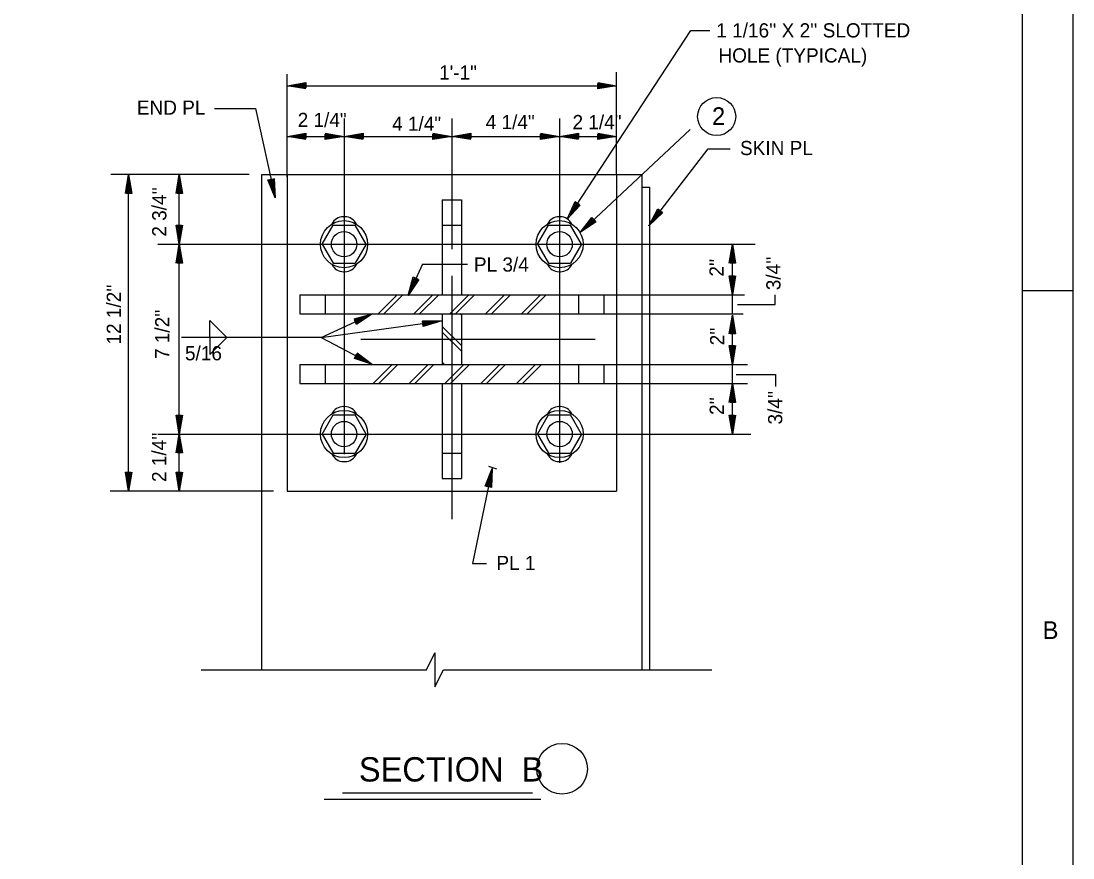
# Model space of a CAD drawing. Extents: x 0.1 to 13.5, y 0.1 to 9.5.
# Drawn here: x 10 to 13.457, y 2.925 to 5.677 of the extents above; entities that cross this region are included whole.
import ezdxf

# ---------------------------------------------------------------- set-up
doc = ezdxf.new("R2010")
doc.units = 0
for name, color, linetype in [('Level 1', 7, 'Continuous'), ('Level 2', 7, 'Continuous'), ('Level 25', 7, 'Continuous'), ('Level 3', 7, 'Continuous'), ('Level 4', 7, 'Continuous'), ('Level 44', 7, 'Continuous'), ('Level 50', 7, 'Continuous')]:
    doc.layers.add(name, color=color, linetype=linetype)

msp = doc.modelspace()

# ---------------------------------------------------------------- linework, layer by layer
at = {"layer": 'Level 1'}
msp.add_line((13.2904, 4.7903), (13.4571, 4.7903), dxfattribs=at)
for points in [[(0.1238, 9.4569), (13.4571, 9.4569), (13.4571, 0.1236), (0.1238, 0.1236)], [(0.6238, 9.2903), (13.2904, 9.2903), (13.2904, 0.2903), (0.6238, 0.2903)]]:
    msp.add_lwpolyline(points, close=True, dxfattribs=at)
msp.add_lwpolyline([(11.3324, 3.5433), (11.3604, 3.5995), (11.3604, 3.4872), (11.3885, 3.5433)], dxfattribs=at)
at = {"layer": 'Level 2'}
for p, q in [((10.8741, 5.4643), (11.9574, 5.4643)), ((11.0616, 5.3566), (11.0616, 4.2531)), ((11.4158, 5.3566), (11.4158, 4.9263)), ((11.7699, 5.3566), (11.7699, 4.2246)), ((10.8741, 5.2976), (11.0616, 5.2976)), ((11.0616, 5.2976), (11.4158, 5.2976)), ((11.4158, 5.2976), (11.7699, 5.2976)), ((11.7699, 5.2976), (11.9574, 5.2976)), ((10.3533, 4.1309), (10.3533, 5.1726)), ((10.5199, 4.943), (10.5199, 5.1726)), ((10.7908, 3.5433), (10.7908, 5.1726)), ((10.7908, 5.1726), (12.0408, 5.1726)), ((10.8741, 5.1726), (10.8741, 4.1309)), ((11.9574, 5.1726), (11.9574, 4.1309)), ((12.0408, 3.5433), (12.0408, 5.1726)), ((12.0408, 5.1309), (12.0668, 5.1309)), ((12.0668, 3.5433), (12.0668, 5.1309)), ((11.3845, 5.0893), (11.447, 5.0893)), ((11.3845, 5.0893), (11.3845, 4.7768)), ((11.447, 5.0893), (11.447, 4.7768)), ((11.0594, 5.0332), (11.0642, 5.0332)), ((11.7678, 5.0332), (11.7725, 5.0332)), ((10.9893, 4.943), (11.0256, 5.0058)), ((11.0256, 5.0058), (11.0977, 5.0058)), ((11.1339, 4.943), (11.0977, 5.0058)), ((11.3845, 5.0059), (11.447, 5.0059)), ((11.6977, 4.943), (11.7339, 5.0058)), ((11.7339, 5.0058), (11.806, 5.0058)), ((11.8422, 4.943), (11.806, 5.0058)), ((10.4497, 4.943), (12.4128, 4.943)), ((10.5199, 4.3188), (10.5199, 4.943)), ((10.9893, 4.943), (11.0256, 4.8803)), ((11.0616, 4.943), (11.0616, 4.943)), ((11.0616, 4.943), (11.0616, 4.943)), ((11.0616, 4.943), (11.0616, 4.943)), ((11.1339, 4.943), (11.0977, 4.8803)), ((11.6977, 4.943), (11.7339, 4.8803)), ((11.7699, 4.943), (11.7699, 4.943)), ((11.7699, 4.943), (11.7699, 4.943)), ((11.7699, 4.943), (11.7699, 4.943)), ((11.7699, 4.943), (11.7699, 4.943)), ((11.8422, 4.943), (11.806, 4.8803)), ((12.3377, 4.7768), (12.3377, 4.943)), ((11.0256, 4.8803), (11.0977, 4.8803)), ((11.7339, 4.8803), (11.806, 4.8803)), ((11.0597, 4.8526), (11.0642, 4.8525)), ((11.7681, 4.8526), (11.7725, 4.8525)), ((11.4158, 4.8387), (11.4158, 4.0391)), ((10.9158, 4.7768), (11.9158, 4.7768)), ((10.9158, 4.7768), (10.9158, 4.7143)), ((10.9991, 4.7768), (10.9991, 4.7143)), ((11.8324, 4.7768), (11.8324, 4.7143)), ((11.9158, 4.7768), (11.9158, 4.7143)), ((12.3377, 4.7143), (12.3377, 4.7768)), ((10.9158, 4.7143), (11.9158, 4.7143)), ((11.3845, 4.7143), (11.3845, 4.5476)), ((11.447, 4.7143), (11.447, 4.5476)), ((12.3377, 4.5476), (12.3377, 4.7102)), ((10.9158, 4.5476), (11.9158, 4.5476)), ((10.9158, 4.5476), (10.9158, 4.4851)), ((10.9991, 4.5476), (10.9991, 4.4851)), ((11.8324, 4.5476), (11.8324, 4.4851)), ((11.9158, 4.5476), (11.9158, 4.4851)), ((12.3377, 4.4851), (12.3377, 4.5476)), ((10.9158, 4.4851), (11.9158, 4.4851)), ((11.3845, 4.4851), (11.3845, 4.1726)), ((11.447, 4.4851), (11.447, 4.1726)), ((12.3377, 4.3188), (12.3377, 4.4851)), ((11.0594, 4.4089), (11.0642, 4.4089)), ((11.7678, 4.4089), (11.7725, 4.4089)), ((10.9893, 4.3188), (11.0256, 4.3816)), ((11.0256, 4.3816), (11.0977, 4.3816)), ((11.1339, 4.3188), (11.0977, 4.3816)), ((11.6977, 4.3188), (11.7339, 4.3816)), ((11.7339, 4.3816), (11.806, 4.3816)), ((11.8422, 4.3188), (11.806, 4.3816)), ((10.4497, 4.3188), (12.3985, 4.3188)), ((10.5199, 4.1309), (10.5199, 4.3188)), ((10.9893, 4.3188), (11.0256, 4.2561)), ((11.0616, 4.3188), (11.0616, 4.3188)), ((11.0616, 4.3188), (11.0616, 4.3188)), ((11.0616, 4.3188), (11.0616, 4.3188)), ((11.0616, 4.3188), (11.0616, 4.3188)), ((11.0616, 4.3188), (11.0616, 4.3188)), ((11.1339, 4.3188), (11.0977, 4.2561)), ((11.6977, 4.3188), (11.7339, 4.2561)), ((11.7699, 4.3188), (11.7699, 4.3188)), ((11.7699, 4.3188), (11.7699, 4.3188)), ((11.7699, 4.3188), (11.7699, 4.3188)), ((11.7699, 4.3188), (11.7699, 4.3188)), ((11.7699, 4.3188), (11.7699, 4.3188)), ((11.7699, 4.3188), (11.7699, 4.3188)), ((11.8422, 4.3188), (11.806, 4.2561)), ((11.0256, 4.2561), (11.0977, 4.2561)), ((11.3845, 4.2559), (11.447, 4.2559)), ((11.7339, 4.2561), (11.806, 4.2561)), ((11.0597, 4.2284), (11.0642, 4.2283)), ((11.7681, 4.2284), (11.7725, 4.2283)), ((11.3845, 4.1726), (11.447, 4.1726)), ((10.8741, 4.1309), (11.9574, 4.1309)), ((10.592, 3.5433), (11.3324, 3.5433)), ((11.3885, 3.5433), (12.2705, 3.5433))]:
    msp.add_line(p, q, dxfattribs=at)
for points in [[(11.1733, 4.7143), (11.2359, 4.7768)], [(11.1922, 4.7143), (11.2547, 4.7768)], [(11.2912, 4.7143), (11.3537, 4.7768)], [(11.31, 4.7143), (11.3726, 4.7768)], [(11.4091, 4.7143), (11.4716, 4.7768)], [(11.4279, 4.7143), (11.4904, 4.7768)], [(11.5269, 4.7143), (11.5894, 4.7768)], [(11.5458, 4.7143), (11.6083, 4.7768)], [(11.6447, 4.7143), (11.7073, 4.7768)], [(11.6636, 4.7143), (11.7261, 4.7768)], [(11.447, 4.7093), (11.442, 4.7143)], [(11.447, 4.6103), (11.3845, 4.6728)], [(11.447, 4.5914), (11.3845, 4.6539)], [(11.1572, 4.4851), (11.2197, 4.5476)], [(11.1761, 4.4851), (11.2386, 4.5476)], [(11.2751, 4.4851), (11.3376, 4.5476)], [(11.2939, 4.4851), (11.3564, 4.5476)], [(11.3918, 4.5476), (11.3845, 4.5549)], [(11.3929, 4.4851), (11.4554, 4.5476)], [(11.4118, 4.4851), (11.4743, 4.5476)], [(11.5108, 4.4851), (11.5733, 4.5476)], [(11.5296, 4.4851), (11.5921, 4.5476)], [(11.6286, 4.4851), (11.6911, 4.5476)], [(11.6475, 4.4851), (11.71, 4.5476)]]:
    msp.add_lwpolyline(points, dxfattribs=at)
for centre, radius in [((11.0616, 4.943), 0.0775), ((11.7699, 4.943), 0.0775), ((11.0616, 4.943), 0.0417), ((11.7699, 4.943), 0.0417), ((11.0616, 4.3188), 0.0775), ((11.7699, 4.3188), 0.0775), ((11.0616, 4.3188), 0.0417), ((11.7699, 4.3188), 0.0417)]:
    msp.add_circle(centre, radius, dxfattribs=at)
for centre, start, end in [((11.0594, 4.9915), 90, 154.2596), ((11.0642, 4.9915), 25.204, 90), ((11.7678, 4.9915), 90, 154.2596), ((11.7725, 4.9915), 25.204, 90), ((11.0597, 4.8943), 205.7404, 270), ((11.0642, 4.8942), 270, 334.796), ((11.7681, 4.8943), 205.7404, 270), ((11.7725, 4.8942), 270, 334.796), ((11.0594, 4.3673), 90, 154.2596), ((11.0642, 4.3673), 25.204, 90), ((11.7678, 4.3673), 90, 154.2596), ((11.7725, 4.3673), 25.204, 90), ((11.0597, 4.2701), 205.7404, 270), ((11.0642, 4.27), 270, 334.796), ((11.7681, 4.2701), 205.7404, 270), ((11.7725, 4.27), 270, 334.796)]:
    msp.add_arc(centre, 0.0417, start, end, dxfattribs=at)
at = {"layer": 'Level 25'}
msp.add_line((11.117, 4.6309), (11.8864, 4.6309), dxfattribs=at)
at = {"layer": 'Level 3'}
for p, q in [((11.8047, 5.0399), (12.2017, 5.646)), ((12.2017, 5.646), (12.2637, 5.646)), ((10.8741, 5.1647), (10.8741, 5.5018)), ((11.9574, 5.1725), (11.9574, 5.5087)), ((11.3984, 5.2976), (11.3984, 5.2976)), ((11.4158, 5.2976), (11.4158, 5.2976)), ((11.4158, 5.2976), (11.4158, 5.2976)), ((11.4331, 5.2976), (11.4331, 5.2976)), ((12.1989, 5.3201), (11.8378, 4.9811)), ((12.0632, 5.0038), (12.2578, 5.2565)), ((12.2578, 5.2565), (12.3305, 5.2565)), ((10.8312, 5.1127), (10.8312, 5.1127)), ((10.8349, 5.0958), (10.8349, 5.0958)), ((11.7952, 5.0254), (11.7952, 5.0254)), ((11.8047, 5.0399), (11.8047, 5.0399)), ((12.0738, 5.0175), (12.0738, 5.0175)), ((11.8378, 4.9811), (11.8378, 4.9811)), ((11.8504, 4.993), (11.8504, 4.993)), ((12.0632, 5.0038), (12.0632, 5.0038)), ((10.5199, 4.9604), (10.5199, 4.9604)), ((10.5199, 4.943), (10.5199, 4.943)), ((10.5199, 4.943), (10.5199, 4.943)), ((10.5199, 4.9257), (10.5199, 4.9257)), ((12.3377, 4.943), (12.3377, 4.943)), ((12.3377, 4.9257), (12.3377, 4.9257)), ((11.3193, 4.8775), (11.2721, 4.7746)), ((11.3193, 4.8775), (11.4672, 4.8775)), ((11.2721, 4.7746), (11.2721, 4.7746)), ((11.2793, 4.7904), (11.2793, 4.7904)), ((11.7119, 4.7768), (12.3772, 4.7768)), ((12.3377, 4.7941), (12.3377, 4.7941)), ((12.3377, 4.7768), (12.3377, 4.7768)), ((12.478, 4.7446), (12.478, 4.7762)), ((12.3541, 4.7446), (12.478, 4.7446)), ((10.9863, 4.6366), (11.1554, 4.7143)), ((11.1396, 4.707), (11.1396, 4.707)), ((11.1554, 4.7143), (11.1554, 4.7143)), ((11.7159, 4.7143), (12.3736, 4.7143)), ((12.3377, 4.7102), (12.3377, 4.7102)), ((10.9863, 4.6366), (11.3825, 4.6906)), ((11.3653, 4.6883), (11.3653, 4.6883)), ((11.3825, 4.6906), (11.3825, 4.6906)), ((12.3377, 4.6928), (12.3377, 4.6928)), ((10.9863, 4.6366), (11.1554, 4.5476)), ((12.3377, 4.5649), (12.3377, 4.5649)), ((11.14, 4.5557), (11.14, 4.5557)), ((11.1554, 4.5476), (11.1554, 4.5476)), ((11.7198, 4.5476), (12.3879, 4.5476)), ((12.3377, 4.5476), (12.3377, 4.5476)), ((12.3506, 4.5151), (12.4792, 4.5151)), ((12.4792, 4.5151), (12.4792, 4.4749)), ((11.7198, 4.4851), (12.3879, 4.4851)), ((12.3377, 4.4851), (12.3377, 4.4851)), ((12.3377, 4.4678), (12.3377, 4.4678)), ((10.5199, 4.3362), (10.5199, 4.3362)), ((12.3377, 4.3362), (12.3377, 4.3362)), ((10.5199, 4.3188), (10.5199, 4.3188)), ((10.5199, 4.3188), (10.5199, 4.3188)), ((10.5199, 4.3015), (10.5199, 4.3015)), ((12.3377, 4.3188), (12.3377, 4.3188)), ((11.5485, 4.2059), (11.4835, 3.8932)), ((11.5362, 4.2129), (11.5626, 4.2041)), ((11.545, 4.1889), (11.545, 4.1889)), ((11.5485, 4.2059), (11.5485, 4.2059)), ((10.8295, 4.1309), (10.2927, 4.1309)), ((10.3533, 4.1483), (10.3533, 4.1483)), ((10.3533, 4.1309), (10.3533, 4.1309)), ((10.5199, 4.1483), (10.5199, 4.1483)), ((10.5199, 4.1309), (10.5199, 4.1309)), ((11.4835, 3.8932), (11.5296, 3.8932)), ((10.9963, 3.1181), (11.7082, 3.1181)), ((11.0568, 3.139), (11.6814, 3.139))]:
    msp.add_line(p, q, dxfattribs=at)
for points in [[(10.6356, 5.389), (10.7704, 5.389), (10.8349, 5.0958)], [(11.3534, 5.3079), (11.4158, 5.2976), (11.3534, 5.2873), (11.3534, 5.3049), (11.3984, 5.2976), (11.3561, 5.2906), (11.3561, 5.3019), (11.3818, 5.2976), (11.3588, 5.2939), (11.3588, 5.2986), (11.3644, 5.2976)], [(11.4781, 5.2873), (11.4158, 5.2976), (11.4781, 5.3079), (11.4781, 5.2903), (11.4331, 5.2976), (11.4754, 5.3046), (11.4754, 5.2933), (11.4498, 5.2976), (11.4728, 5.3013), (11.4728, 5.2966), (11.4671, 5.2976)], [(10.8316, 5.1589), (10.8349, 5.0958), (10.8114, 5.1544), (10.8287, 5.1582), (10.8312, 5.1127), (10.8153, 5.1525), (10.8263, 5.155), (10.8276, 5.129), (10.8191, 5.1506), (10.8237, 5.1516), (10.8239, 5.1459)], [(11.838, 5.0719), (11.7952, 5.0254), (11.8208, 5.0832), (11.8355, 5.0736), (11.8047, 5.0399), (11.8221, 5.0792), (11.8316, 5.073), (11.8139, 5.0539), (11.8234, 5.0751), (11.8273, 5.0726), (11.8234, 5.0684)], [(12.1094, 5.0469), (12.0632, 5.0038), (12.093, 5.0595), (12.107, 5.0487), (12.0738, 5.0175), (12.094, 5.0554), (12.103, 5.0484), (12.0839, 5.0308), (12.0951, 5.0512), (12.0988, 5.0484), (12.0945, 5.0445)], [(11.8903, 5.0163), (11.8378, 4.9811), (11.8761, 5.0313), (11.8882, 5.0184), (11.8504, 4.993), (11.8765, 5.0271), (11.8842, 5.0188), (11.8626, 5.0044), (11.8768, 5.0228), (11.88, 5.0194), (11.8752, 5.0163)], [(10.5303, 5.0054), (10.5199, 4.943), (10.5096, 5.0054), (10.5273, 5.0054), (10.5199, 4.9604), (10.5129, 5.0027), (10.5243, 5.0027), (10.5199, 4.977), (10.5163, 5), (10.5209, 5), (10.5199, 4.9944)], [(10.5096, 4.8807), (10.5199, 4.943), (10.5303, 4.8807), (10.5126, 4.8807), (10.5199, 4.9257), (10.5269, 4.8834), (10.5156, 4.8834), (10.5199, 4.909), (10.5236, 4.886), (10.5189, 4.886), (10.5199, 4.8917)], [(12.3273, 4.8807), (12.3377, 4.943), (12.348, 4.8807), (12.3303, 4.8807), (12.3377, 4.9257), (12.3447, 4.8834), (12.3333, 4.8834), (12.3377, 4.909), (12.3413, 4.886), (12.3367, 4.886), (12.3377, 4.8917)], [(11.3074, 4.827), (11.2721, 4.7746), (11.2887, 4.8356), (11.3047, 4.8282), (11.2793, 4.7904), (11.2906, 4.8318), (11.3009, 4.827), (11.2862, 4.8055), (11.2925, 4.828), (11.2967, 4.826), (11.2935, 4.8213)], [(12.348, 4.8391), (12.3377, 4.7768), (12.3273, 4.8391), (12.345, 4.8391), (12.3377, 4.7941), (12.3307, 4.8364), (12.342, 4.8364), (12.3377, 4.8108), (12.334, 4.8338), (12.3387, 4.8338), (12.3377, 4.8281)], [(11.0944, 4.6976), (11.1554, 4.7143), (11.103, 4.6789), (11.0957, 4.6949), (11.1396, 4.707), (11.1041, 4.683), (11.0993, 4.6933), (11.1245, 4.7001), (11.1051, 4.6871), (11.1032, 4.6914), (11.1087, 4.6928)], [(12.3273, 4.6478), (12.3377, 4.7102), (12.348, 4.6478), (12.3303, 4.6478), (12.3377, 4.6928), (12.3447, 4.6505), (12.3333, 4.6505), (12.3377, 4.6762), (12.3413, 4.6532), (12.3367, 4.6532), (12.3377, 4.6588)], [(11.3193, 4.6924), (11.3825, 4.6906), (11.3221, 4.672), (11.3197, 4.6895), (11.3653, 4.6883), (11.3243, 4.6756), (11.3228, 4.6869), (11.3488, 4.686), (11.3265, 4.6793), (11.3259, 4.6839), (11.3316, 4.6837)], [(12.348, 4.6099), (12.3377, 4.5476), (12.3273, 4.6099), (12.345, 4.6099), (12.3377, 4.5649), (12.3307, 4.6073), (12.342, 4.6073), (12.3377, 4.5816), (12.334, 4.6046), (12.3387, 4.6046), (12.3377, 4.5989)], [(11.105, 4.5858), (11.1554, 4.5476), (11.0954, 4.5675), (11.1036, 4.5831), (11.14, 4.5557), (11.0993, 4.5692), (11.1046, 4.5792), (11.1253, 4.5634), (11.1032, 4.5709), (11.1054, 4.575), (11.1099, 4.5715)], [(12.3273, 4.4228), (12.3377, 4.4851), (12.348, 4.4228), (12.3303, 4.4228), (12.3377, 4.4678), (12.3447, 4.4254), (12.3333, 4.4254), (12.3377, 4.4511), (12.3413, 4.4281), (12.3367, 4.4281), (12.3377, 4.4338)], [(10.5303, 4.3812), (10.5199, 4.3188), (10.5096, 4.3812), (10.5273, 4.3812), (10.5199, 4.3362), (10.5129, 4.3785), (10.5243, 4.3785), (10.5199, 4.3528), (10.5163, 4.3758), (10.5209, 4.3758), (10.5199, 4.3702)], [(12.348, 4.3812), (12.3377, 4.3188), (12.3273, 4.3812), (12.345, 4.3812), (12.3377, 4.3362), (12.3307, 4.3785), (12.342, 4.3785), (12.3377, 4.3528), (12.334, 4.3758), (12.3387, 4.3758), (12.3377, 4.3702)], [(10.5096, 4.2565), (10.5199, 4.3188), (10.5303, 4.2565), (10.5126, 4.2565), (10.5199, 4.3015), (10.5269, 4.2592), (10.5156, 4.2592), (10.5199, 4.2848), (10.5236, 4.2618), (10.5189, 4.2618), (10.5199, 4.2675)], [(10.3636, 4.1933), (10.3533, 4.1309), (10.3429, 4.1933), (10.3606, 4.1933), (10.3533, 4.1483), (10.3463, 4.1906), (10.3576, 4.1906), (10.3533, 4.1649), (10.3496, 4.1879), (10.3543, 4.1879), (10.3533, 4.1823)], [(10.5303, 4.1933), (10.5199, 4.1309), (10.5096, 4.1933), (10.5273, 4.1933), (10.5199, 4.1483), (10.5129, 4.1906), (10.5243, 4.1906), (10.5199, 4.1649), (10.5163, 4.1879), (10.5209, 4.1879), (10.5199, 4.1823)], [(11.5257, 4.1469), (11.5485, 4.2059), (11.5459, 4.1427), (11.5287, 4.1463), (11.545, 4.1889), (11.5432, 4.146), (11.5321, 4.1483), (11.5416, 4.1726), (11.5405, 4.1493), (11.5359, 4.1503), (11.5381, 4.1556)]]:
    msp.add_lwpolyline(points, dxfattribs=at)
for centre, radius in [((12.2861, 5.3629), 0.0625), ((11.7781, 3.2179), 0.0833)]:
    msp.add_circle(centre, radius, dxfattribs=at)
at = {"layer": 'Level 4'}
for p, q in [((10.6208, 4.6923), (10.6767, 4.6364)), ((10.6208, 4.636), (10.6208, 4.6923)), ((10.9863, 4.6366), (10.527, 4.6366)), ((10.6208, 4.6372), (10.6208, 4.5809)), ((10.6208, 4.5809), (10.6767, 4.6368))]:
    msp.add_line(p, q, dxfattribs=at)
at = {"layer": 'Level 44'}
msp.add_line((10.7499, 5.1726), (10.2947, 5.1726), dxfattribs=at)
at = {"layer": 'Level 50'}
for p, q in [((10.8741, 5.4643), (10.8741, 5.4643)), ((10.8914, 5.4643), (10.8914, 5.4643)), ((11.9401, 5.4643), (11.9401, 5.4643)), ((11.9574, 5.4643), (11.9574, 5.4643)), ((10.8741, 5.2976), (10.8741, 5.2976)), ((10.8914, 5.2976), (10.8914, 5.2976)), ((11.0443, 5.2976), (11.0443, 5.2976)), ((11.0616, 5.2976), (11.0616, 5.2976)), ((11.0616, 5.2976), (11.0616, 5.2976)), ((11.0616, 5.2976), (11.0616, 5.2976)), ((11.0789, 5.2976), (11.0789, 5.2976)), ((11.0789, 5.2976), (11.0789, 5.2976)), ((11.7526, 5.2976), (11.7526, 5.2976)), ((11.7699, 5.2976), (11.7699, 5.2976)), ((11.7699, 5.2976), (11.7699, 5.2976)), ((11.7873, 5.2976), (11.7873, 5.2976)), ((11.9401, 5.2976), (11.9401, 5.2976)), ((11.9574, 5.2976), (11.9574, 5.2976)), ((10.3533, 5.1726), (10.3533, 5.1726)), ((10.3533, 5.1726), (10.3533, 5.1726)), ((10.3533, 5.1553), (10.3533, 5.1553)), ((10.3533, 5.1553), (10.3533, 5.1553)), ((10.5199, 5.1726), (10.5199, 5.1726)), ((10.5199, 5.1726), (10.5199, 5.1726)), ((10.5199, 5.1553), (10.5199, 5.1553)), ((10.5199, 5.1553), (10.5199, 5.1553))]:
    msp.add_line(p, q, dxfattribs=at)
for points in [[(10.9364, 5.4539), (10.8741, 5.4643), (10.9364, 5.4746), (10.9364, 5.4569), (10.8914, 5.4643), (10.9338, 5.4713), (10.9338, 5.4599), (10.9081, 5.4643), (10.9311, 5.4679), (10.9311, 5.4633), (10.9254, 5.4643)], [(11.8951, 5.4746), (11.9574, 5.4643), (11.8951, 5.4539), (11.8951, 5.4716), (11.9401, 5.4643), (11.8978, 5.4573), (11.8978, 5.4686), (11.9234, 5.4643), (11.9004, 5.4606), (11.9004, 5.4653), (11.9061, 5.4643)], [(10.9364, 5.2873), (10.8741, 5.2976), (10.9364, 5.3079), (10.9364, 5.2903), (10.8914, 5.2976), (10.9338, 5.3046), (10.9338, 5.2933), (10.9081, 5.2976), (10.9311, 5.3013), (10.9311, 5.2966), (10.9254, 5.2976)], [(10.9993, 5.3079), (11.0616, 5.2976), (10.9993, 5.2873), (10.9993, 5.3049), (11.0443, 5.2976), (11.0019, 5.2906), (11.0019, 5.3019), (11.0276, 5.2976), (11.0046, 5.2939), (11.0046, 5.2986), (11.0103, 5.2976)], [(11.1239, 5.2873), (11.0616, 5.2976), (11.1239, 5.3079), (11.1239, 5.2903), (11.0789, 5.2976), (11.1213, 5.3046), (11.1213, 5.2933), (11.0956, 5.2976), (11.1186, 5.3013), (11.1186, 5.2966), (11.1129, 5.2976)], [(11.1239, 5.2873), (11.0616, 5.2976), (11.1239, 5.3079), (11.1239, 5.2903), (11.0789, 5.2976), (11.1213, 5.3046), (11.1213, 5.2933), (11.0956, 5.2976), (11.1186, 5.3013), (11.1186, 5.2966), (11.1129, 5.2976)], [(11.7076, 5.3079), (11.7699, 5.2976), (11.7076, 5.2873), (11.7076, 5.3049), (11.7526, 5.2976), (11.7103, 5.2906), (11.7103, 5.3019), (11.7359, 5.2976), (11.7129, 5.2939), (11.7129, 5.2986), (11.7186, 5.2976)], [(11.8323, 5.2873), (11.7699, 5.2976), (11.8323, 5.3079), (11.8323, 5.2903), (11.7873, 5.2976), (11.8296, 5.3046), (11.8296, 5.2933), (11.8039, 5.2976), (11.8269, 5.3013), (11.8269, 5.2966), (11.8213, 5.2976)], [(11.8951, 5.3079), (11.9574, 5.2976), (11.8951, 5.2873), (11.8951, 5.3049), (11.9401, 5.2976), (11.8978, 5.2906), (11.8978, 5.3019), (11.9234, 5.2976), (11.9004, 5.2939), (11.9004, 5.2986), (11.9061, 5.2976)], [(10.3429, 5.1103), (10.3533, 5.1726), (10.3636, 5.1103), (10.3459, 5.1103), (10.3533, 5.1553), (10.3603, 5.1129), (10.3489, 5.1129), (10.3533, 5.1386), (10.3569, 5.1156), (10.3523, 5.1156), (10.3533, 5.1213)], [(10.3429, 5.1103), (10.3533, 5.1726), (10.3636, 5.1103), (10.3459, 5.1103), (10.3533, 5.1553), (10.3603, 5.1129), (10.3489, 5.1129), (10.3533, 5.1386), (10.3569, 5.1156), (10.3523, 5.1156), (10.3533, 5.1213)], [(10.5096, 5.1103), (10.5199, 5.1726), (10.5303, 5.1103), (10.5126, 5.1103), (10.5199, 5.1553), (10.5269, 5.1129), (10.5156, 5.1129), (10.5199, 5.1386), (10.5236, 5.1156), (10.5189, 5.1156), (10.5199, 5.1213)], [(10.5096, 5.1103), (10.5199, 5.1726), (10.5303, 5.1103), (10.5126, 5.1103), (10.5199, 5.1553), (10.5269, 5.1129), (10.5156, 5.1129), (10.5199, 5.1386), (10.5236, 5.1156), (10.5189, 5.1156), (10.5199, 5.1213)]]:
    msp.add_lwpolyline(points, dxfattribs=at)

# ---------------------------------------------------------------- texts
at = {"layer": 'Level 1'}
msp.add_text('B', height=0.0584, dxfattribs=at).set_placement((13.3574, 3.6447))
at = {"layer": 'Level 3'}
for s, height, p in [("1 1/16'' X 2'' SLOTTED", 0.046667, (12.285, 5.623)), ('HOLE (TYPICAL)', 0.046667, (12.292, 5.5406)), ('1\'-1"', 0.04667, (11.3739, 5.4844)), ('END PL', 0.04667, (10.3806, 5.3689)), ('2', 0.0583, (12.2708, 5.3349)), ('2 1/4"', 0.04667, (10.9091, 5.3284)), ('4 1/4"', 0.04667, (11.2195, 5.316)), ('4 1/4"', 0.04667, (11.5271, 5.3214)), ('2 1/4"', 0.04667, (11.8124, 5.3213)), ('SKIN PL', 0.04667, (12.3629, 5.2361)), ('PL 3/4', 0.04667, (11.4884, 4.853)), ('5/16', 0.04667, (10.5388, 4.5612)), ('PL 1', 0.04667, (11.5623, 3.8715)), ('SECTION  B', 0.08, (11.1103, 3.1761))]:
    msp.add_text(s, height=height, dxfattribs=at).set_placement(p)
for s, p in [("2 3/4''", (10.4776, 4.9679)), ("2''", (12.3091, 4.8366)), ("3/4''", (12.4959, 4.7918)), ("12 1/2''", (10.3282, 4.6132)), ("7 1/2''", (10.4874, 4.5655)), ("2''", (12.3111, 4.6105)), ("2''", (12.3098, 4.3816)), ("3/4''", (12.5017, 4.3502)), ("2 1/4''", (10.4772, 4.1611))]:
    msp.add_text(s, height=0.04667, rotation=90, dxfattribs=at).set_placement(p)

doc.saveas('drawing.dxf')
